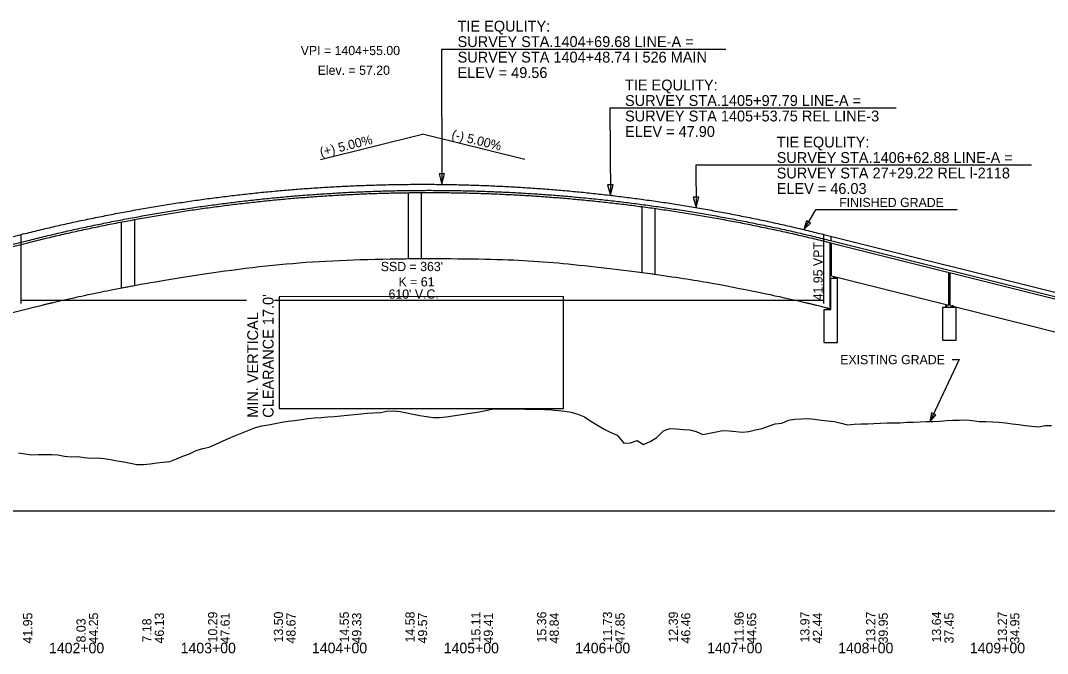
# Model space of a CAD drawing. Extents: x 2360994 to 2383826, y 330623 to 403123.
# Drawn here: x 2372575 to 2373355, y 371764 to 372245 of the extents above; entities that cross this region are included whole.
import ezdxf

# ---------------------------------------------------------------- set-up
doc = ezdxf.new("R2010")
doc.units = 0
for name, color, linetype in [('RD_DDB_GradeTX', 7, 'Continuous'), ('RD_DDB_Profile_EX', 7, 'Continuous'), ('RD_DDB_Profile_Lbl', 7, 'Continuous'), ('RD_DDB_Profile_PR', 7, 'Continuous'), ('RD_DDB_StaTX', 7, 'Continuous'), ('RD_DDB_StripGrade', 7, 'Continuous'), ('RD_DDB_VCLbl', 7, 'Continuous'), ('RD_GPK_Profile_Cell', 7, 'Continuous'), ('RD_TX_Profile', 7, 'Continuous'), ('RD_XS_Bridge', 7, 'Continuous')]:
    doc.layers.add(name, color=color, linetype=linetype)

msp = doc.modelspace()

# ---------------------------------------------------------------- linework, layer by layer
at = {"layer": 'RD_DDB_GradeTX'}
for p in [(2372802.95, 372139.48), (2372958.18, 372139.48)]:
    msp.add_line(p, (2372880.57, 372158.88), dxfattribs=at)
at = {"layer": 'RD_DDB_Profile_EX'}
for points in [[(2372573.57, 371916.75), (2372578.57, 371916.05), (2372583.57, 371915.41), (2372588.57, 371915.52), (2372593.57, 371915.64), (2372598.57, 371915.52), (2372603.57, 371915.17), (2372608.57, 371914.39), (2372613.57, 371913.78), (2372618.57, 371913.91), (2372623.57, 371913.26), (2372628.57, 371912.73), (2372633.57, 371912.9), (2372638.57, 371912.49), (2372643.57, 371911.7), (2372648.57, 371910.8), (2372653.57, 371909.99), (2372658.57, 371909.04), (2372663.57, 371908.05), (2372668.57, 371908.04), (2372673.57, 371908.57), (2372678.57, 371909.11), (2372683.57, 371909.65), (2372688.57, 371910.2), (2372693.57, 371912.18), (2372698.57, 371914.36), (2372703.57, 371916.04), (2372708.57, 371918.68), (2372713.57, 371920.08), (2372718.57, 371921.1), (2372723.57, 371923.41), (2372728.57, 371925.77), (2372733.57, 371927.84), (2372738.57, 371929.86), (2372743.57, 371931.9), (2372748.57, 371933.95), (2372753.57, 371936.04), (2372758.57, 371937.2), (2372763.57, 371938.15), (2372768.57, 371939.11), (2372773.57, 371940.08), (2372778.57, 371940.79), (2372783.57, 371941.48), (2372788.57, 371942.14), (2372793.57, 371942.79), (2372798.57, 371943.3), (2372803.57, 371943.68), (2372808.57, 371944.07), (2372813.57, 371944.46), (2372818.57, 371944.93), (2372823.57, 371945.42), (2372828.57, 371945.93), (2372833.57, 371946.38), (2372838.57, 371946.83), (2372843.57, 371947.22), (2372848.57, 371947.37), (2372853.57, 371948.38), (2372858.57, 371948.76), (2372863.57, 371948.1), (2372868.57, 371947.1), (2372873.57, 371946.18)], [(2372873.57, 371946.18), (2372878.57, 371945.19), (2372883.57, 371944.46), (2372888.57, 371943.56), (2372893.57, 371943.59), (2372898.57, 371944.18), (2372903.57, 371944.88), (2372908.57, 371945.56), (2372913.57, 371946.34), (2372918.57, 371947.12), (2372923.57, 371947.99), (2372928.57, 371949.04), (2372933.57, 371949.85), (2372938.57, 371950.13), (2372943.57, 371950.35), (2372948.57, 371950.26), (2372953.57, 371950.16), (2372958.57, 371950.05), (2372963.57, 371949.96), (2372968.57, 371949.87), (2372973.57, 371949.76), (2372978.57, 371949.52), (2372983.57, 371949.03), (2372988.57, 371948.53), (2372993.57, 371947.59), (2372998.57, 371946.29), (2373003.57, 371944.13), (2373008.57, 371940.76), (2373013.57, 371937.7), (2373018.57, 371934.68), (2373023.57, 371932.37), (2373028.57, 371930.22), (2373033.57, 371924.25), (2373038.57, 371924.34), (2373043.57, 371926.11), (2373048.57, 371923.15), (2373053.57, 371925.37), (2373058.57, 371928.46), (2373063.57, 371933.52), (2373068.57, 371935.29), (2373073.57, 371934.95), (2373078.57, 371934.6), (2373083.57, 371934.15), (2373088.57, 371933.09), (2373093.57, 371930.85), (2373098.57, 371931.74), (2373103.57, 371932.77), (2373108.57, 371933.8), (2373113.57, 371933.45), (2373118.57, 371932.91), (2373123.57, 371932.38), (2373128.57, 371933.07), (2373133.57, 371934.18), (2373138.57, 371935.31), (2373143.57, 371937.03), (2373148.57, 371938.81), (2373153.57, 371939.31), (2373158.57, 371941.61), (2373163.57, 371942.28), (2373168.57, 371942.63), (2373173.57, 371942.97), (2373178.57, 371942.42), (2373183.57, 371941.73), (2373188.57, 371941.1), (2373193.57, 371940.52), (2373198.57, 371939.3), (2373203.57, 371938.07), (2373208.57, 371938.66), (2373213.57, 371938.73), (2373218.57, 371938.79), (2373223.57, 371939.1), (2373228.57, 371939.4), (2373233.57, 371939.62), (2373238.57, 371939.55), (2373243.57, 371939.57), (2373248.57, 371939.99), (2373253.57, 371940.16), (2373258.57, 371940.32), (2373263.57, 371940.49), (2373268.57, 371940.65), (2373273.57, 371940.81), (2373278.57, 371941.43), (2373283.57, 371941.5), (2373288.57, 371941.66), (2373293.57, 371941.82), (2373298.57, 371941.44), (2373303.57, 371940.53), (2373308.57, 371940.63), (2373313.57, 371940.45), (2373318.57, 371940.09), (2373323.57, 371939.49), (2373328.57, 371938.88), (2373333.57, 371938.27), (2373338.57, 371937.66), (2373343.57, 371937.05), (2373348.57, 371936.44), (2373353.57, 371937.64), (2373358.57, 371937.56)]]:
    msp.add_lwpolyline(points, dxfattribs=at)
at = {"layer": 'RD_DDB_Profile_PR'}
for p, q in [((2372206.57, 371990.38), (2372575.57, 372082.63)), ((2373185.57, 372082.63), (2373396.07, 372030.01))]:
    msp.add_line(p, q, dxfattribs=at)
msp.add_spline([(2372575.57, 372082.63), (2372587.77, 372085.62), (2372599.97, 372088.49), (2372612.17, 372091.23), (2372624.37, 372093.86), (2372636.57, 372096.36), (2372648.77, 372098.74), (2372660.97, 372100.99), (2372673.17, 372103.13), (2372685.37, 372105.14), (2372697.57, 372107.03), (2372709.77, 372108.8), (2372721.97, 372110.45), (2372734.17, 372111.97), (2372746.37, 372113.38), (2372758.57, 372114.66), (2372770.77, 372115.82), (2372782.97, 372116.85), (2372795.17, 372117.77), (2372807.37, 372118.56), (2372819.57, 372119.23), (2372831.77, 372119.78), (2372843.97, 372120.21), (2372856.17, 372120.51), (2372868.37, 372120.7), (2372880.57, 372120.76), (2372892.77, 372120.7), (2372904.97, 372120.51), (2372917.17, 372120.21), (2372929.37, 372119.78), (2372941.57, 372119.23), (2372953.77, 372118.56), (2372965.97, 372117.77), (2372978.17, 372116.85), (2372990.37, 372115.82), (2373002.57, 372114.66), (2373014.77, 372113.38), (2373026.97, 372111.97), (2373039.17, 372110.45), (2373051.37, 372108.8), (2373063.57, 372107.03), (2373075.77, 372105.14), (2373087.97, 372103.13), (2373100.17, 372100.99), (2373112.37, 372098.74), (2373124.57, 372096.36), (2373136.77, 372093.86), (2373148.97, 372091.23), (2373161.17, 372088.49), (2373173.37, 372085.62), (2373185.57, 372082.63)], degree=3, dxfattribs=at)
at = {"layer": 'RD_DDB_VCLbl'}
for p, q in [((2372575.57, 372030.13), (2372575.57, 372082.63)), ((2373185.57, 372030.13), (2373185.57, 372082.63)), ((2372575.57, 372032.63), (2372746.9, 372032.63)), ((2372768, 372032.63), (2373185.57, 372032.63))]:
    msp.add_line(p, q, dxfattribs=at)
at = {"layer": 'RD_GPK_Profile_Cell'}
msp.add_line((2368825.57, 371872.88), (2373925.57, 371872.88), dxfattribs=at)
at = {"layer": 'RD_TX_Profile'}
for p, q in [((2373111.11, 372223.22), (2372902.19, 372223.22)), ((2373240.51, 372178.49), (2373029.43, 372178.49)), ((2373343.32, 372135.18), (2373144.67, 372135.18)), ((2373286.69, 372101.46), (2373192.13, 372101.46))]:
    msp.add_line(p, q, dxfattribs=at)
for points in [[(2372902.19, 372223.22), (2372895.1, 372223.22), (2372895.24, 372120.67)], [(2373029.43, 372178.49), (2373022.87, 372178.49), (2373023.35, 372112.4)], [(2373144.67, 372135.18), (2373088.27, 372135.18), (2373088.44, 372103.05)], [(2373192.13, 372101.46), (2373179.27, 372101.46), (2373170.35, 372086.35)], [(2373283.02, 371987.58), (2373288.36, 371987.58), (2373266.11, 371940.27)]]:
    msp.add_lwpolyline(points, dxfattribs=at)
for points in [[(2372893.1, 372128.62), (2372895.24, 372120.67), (2372897.36, 372128.63)], [(2373021.16, 372120.34), (2373023.35, 372112.4), (2373025.42, 372120.37)], [(2373086.27, 372110.99), (2373088.44, 372103.05), (2373090.53, 372111.01)], [(2373172.23, 372093.09), (2373170.35, 372086.35), (2373175.35, 372091.25)], [(2372771.69, 372035.41), (2372771.69, 371950.41), (2372987.68, 371950.41), (2372987.68, 372035.45)], [(2373267.35, 371947.15), (2373266.11, 371940.27), (2373270.63, 371945.61)]]:
    msp.add_lwpolyline(points, close=True, dxfattribs=at)
at = {"layer": 'RD_XS_Bridge'}
for p, q in [((2372869.83, 372064.4), (2372869.83, 372114.4)), ((2372879.83, 372064.49), (2372879.83, 372114.49)), ((2373047.41, 372053.75), (2373047.41, 372103.77)), ((2373057.41, 372052.38), (2373057.41, 372102.4)), ((2372651.91, 372042.09), (2372651.91, 372092.13)), ((2372661.91, 372043.97), (2372661.91, 372094.01)), ((2372227.91, 371989.88), (2372580.57, 372078.05)), ((2372227.91, 371988.22), (2372580.57, 372076.38)), ((2373190.33, 372026.37), (2373190.33, 372076.19)), ((2373190.57, 372078.05), (2373396.07, 372026.67)), ((2373190.57, 372076.38), (2373396.07, 372025.01)), ((2373190.83, 372081.23), (2373190.83, 372077.9)), ((2373191.33, 372051.15), (2373191.33, 372076.19)), ((2373191.33, 372051.15), (2373280.49, 372028.86)), ((2373280.49, 372028.86), (2373280.49, 372053.9)), ((2373281.49, 372028.61), (2373281.49, 372053.65)), ((2373190.83, 372049.47), (2373195.83, 372049.47)), ((2373190.83, 372025.62), (2373190.83, 372049.47)), ((2373195.83, 372000.62), (2373195.83, 372049.47)), ((2373275.99, 372002.49), (2373275.99, 372027.49)), ((2373275.99, 372027.49), (2373280.99, 372027.49)), ((2373280.99, 372027.49), (2373285.99, 372027.49)), ((2373281.49, 372028.61), (2373396.07, 371999.97)), ((2373285.99, 372002.49), (2373285.99, 372027.49)), ((2372483.16, 372001.96), (2372581.12, 372026.45)), ((2373185.83, 372000.62), (2373185.83, 372025.62)), ((2373185.83, 372025.62), (2373190.83, 372025.62)), ((2373185.83, 372000.62), (2373195.83, 372000.62)), ((2373275.99, 372002.49), (2373285.99, 372002.49))]:
    msp.add_line(p, q, dxfattribs=at)
for points in [[(2373193.08, 372049.47), (2373193.08, 372050.72), (2373193.58, 372050.72), (2373193.58, 372049.47)], [(2373188.08, 372025.62), (2373188.08, 372026.87), (2373188.58, 372026.87), (2373188.58, 372025.62)], [(2373278.24, 372027.49), (2373278.24, 372028.74), (2373278.74, 372028.74), (2373278.74, 372027.49)], [(2373283.24, 372027.49), (2373283.24, 372028.74), (2373283.74, 372028.74), (2373283.74, 372027.49)]]:
    msp.add_lwpolyline(points, close=True, dxfattribs=at)
for points in [[(2372580.57, 372078.05), (2372592.77, 372081.04), (2372604.97, 372083.9), (2372617.17, 372086.65), (2372629.37, 372089.27), (2372641.57, 372091.77), (2372653.77, 372094.15), (2372665.97, 372096.41), (2372678.17, 372098.54), (2372690.37, 372100.56), (2372702.57, 372102.45), (2372714.77, 372104.22), (2372726.97, 372105.86), (2372739.17, 372107.39), (2372751.37, 372108.79), (2372763.57, 372110.07), (2372775.77, 372111.23), (2372787.97, 372112.27), (2372800.17, 372113.18), (2372812.37, 372113.98), (2372824.57, 372114.65), (2372836.77, 372115.2), (2372848.97, 372115.62), (2372861.17, 372115.93), (2372873.37, 372116.11), (2372885.57, 372116.17), (2372897.77, 372116.11), (2372909.97, 372115.93), (2372922.17, 372115.62), (2372934.37, 372115.2), (2372946.57, 372114.65), (2372958.77, 372113.98), (2372970.97, 372113.18), (2372983.17, 372112.27), (2372995.37, 372111.23), (2373007.57, 372110.07), (2373019.77, 372108.79), (2373031.97, 372107.39), (2373044.17, 372105.86), (2373056.37, 372104.22), (2373068.57, 372102.45), (2373080.77, 372100.56), (2373092.97, 372098.54), (2373105.17, 372096.41), (2373117.37, 372094.15), (2373129.57, 372091.77), (2373141.77, 372089.27), (2373153.97, 372086.65), (2373166.17, 372083.9), (2373178.37, 372081.04), (2373190.57, 372078.05)], [(2372580.57, 372076.38), (2372592.77, 372079.37), (2372604.97, 372082.24), (2372617.17, 372084.98), (2372629.37, 372087.61), (2372641.57, 372090.11), (2372653.77, 372092.49), (2372665.97, 372094.74), (2372678.17, 372096.88), (2372690.37, 372098.89), (2372702.57, 372100.78), (2372714.77, 372102.55), (2372726.97, 372104.2), (2372739.17, 372105.72), (2372751.37, 372107.13), (2372763.57, 372108.41), (2372775.77, 372109.57), (2372787.97, 372110.6), (2372800.17, 372111.52), (2372812.37, 372112.31), (2372824.57, 372112.98), (2372836.77, 372113.53), (2372848.97, 372113.96), (2372861.17, 372114.26), (2372873.37, 372114.45), (2372885.57, 372114.51), (2372897.77, 372114.45), (2372909.97, 372114.26), (2372922.17, 372113.96), (2372934.37, 372113.53), (2372946.57, 372112.98), (2372958.77, 372112.31), (2372970.97, 372111.52), (2372983.17, 372110.6), (2372995.37, 372109.57), (2373007.57, 372108.41), (2373019.77, 372107.13), (2373031.97, 372105.72), (2373044.17, 372104.2), (2373056.37, 372102.55), (2373068.57, 372100.78), (2373080.77, 372098.89), (2373092.97, 372096.88), (2373105.17, 372094.74), (2373117.37, 372092.49), (2373129.57, 372090.11), (2373141.77, 372087.61), (2373153.97, 372084.98), (2373166.17, 372082.24), (2373178.37, 372079.37), (2373190.57, 372076.38)], [(2372869.83, 372064.37), (2372875.57, 372064.47), (2372879.83, 372064.52)], [(2373047.41, 372053.71), (2373055.55, 372052.67), (2373057.41, 372052.43)], [(2372651.91, 372042.16), (2372653.57, 372042.45), (2372657.57, 372043.15), (2372661.57, 372043.85), (2372661.91, 372043.9)]]:
    msp.add_spline(points, degree=3, dxfattribs=at)
msp.add_open_spline([(2372581.1, 372026.45), (2372584.28, 372027.23), (2372587.46, 372028.01), (2372592.21, 372029.17), (2372593.79, 372029.56), (2372596.96, 372030.31), (2372598.54, 372030.69), (2372603.3, 372031.8), (2372606.47, 372032.53), (2372612.81, 372033.96), (2372628.65, 372037.49), (2372669.87, 372045.86), (2372758.66, 372059.74), (2372834.8, 372064.5), (2372936.33, 372064.5), (2372987.09, 372061.33), (2373063.21, 372051.81), (2373101.27, 372045.87), (2373142.48, 372037.49), (2373158.33, 372033.96), (2373164.66, 372032.53), (2373167.84, 372031.8), (2373172.59, 372030.69), (2373174.17, 372030.31), (2373177.34, 372029.56), (2373178.92, 372029.17), (2373183.41, 372028.08), (2373186.33, 372027.36), (2373190.33, 372026.37)], degree=3, dxfattribs=at)

# ---------------------------------------------------------------- texts
at = {"layer": 'RD_DDB_GradeTX'}
for s, rotation, p in [('(-) 5.00%', 345.96376, (2372902.15, 372155.55)), ('(+) 5.00%', 14.03624, (2372803.5, 372141.68))]:
    msp.add_text(s, height=7, rotation=rotation, dxfattribs=at).set_placement(p)
at = {"layer": 'RD_DDB_Profile_Lbl'}
for s, p in [('VPI = 1404+55.00', (2372788.01, 372218.88)), ('Elev. = 57.20', (2372800.9, 372203.88))]:
    msp.add_text(s, height=7, dxfattribs=at).set_placement(p)
at = {"layer": 'RD_DDB_StaTX'}
for s, p in [('1402+00', (2372596.77, 371764.56)), ('1403+00', (2372696.8, 371764.56)), ('1404+00', (2372796.55, 371764.56)), ('1405+00', (2372896.69, 371764.56)), ('1406+00', (2372996.46, 371764.56)), ('1407+00', (2373096.81, 371764.56)), ('1408+00', (2373196.35, 371764.56)), ('1409+00', (2373296.45, 371764.56))]:
    msp.add_text(s, height=8, dxfattribs=at).set_placement(p)
at = {"layer": 'RD_DDB_StripGrade'}
for s, p in [('41.95 VPT', (2373184.57, 372032.63)), ('41.95', (2372584.08, 371772.02)), ('44.25', (2372634.08, 371772.02)), ('46.13', (2372684.08, 371772.02)), ('10.29', (2372724.59, 371772.81)), ('47.61', (2372734.08, 371772.02)), ('13.50', (2372774.59, 371772.81)), ('48.67', (2372784.08, 371772.02)), ('14.55', (2372824.59, 371772.81)), ('49.33', (2372834.08, 371772.02)), ('14.58', (2372874.59, 371772.81)), ('49.57', (2372884.08, 371772.02)), ('15.11', (2372924.59, 371772.81)), ('49.41', (2372934.08, 371772.02)), ('15.36', (2372974.59, 371772.81)), ('48.84', (2372984.08, 371772.02)), ('11.73', (2373024.59, 371772.81)), ('47.85', (2373034.08, 371772.02)), ('12.39', (2373074.59, 371772.81)), ('46.46', (2373084.08, 371772.02)), ('11.96', (2373124.59, 371772.81)), ('44.65', (2373134.08, 371772.02)), ('13.97', (2373174.59, 371772.81)), ('42.44', (2373184.08, 371772.02)), ('13.27', (2373224.59, 371772.81)), ('39.95', (2373234.08, 371772.02)), ('13.64', (2373274.59, 371772.81)), ('37.45', (2373284.08, 371772.02)), ('13.27', (2373324.59, 371772.81)), ('34.95', (2373334.08, 371772.02)), ('8.03', (2372624.59, 371772.81)), ('7.18', (2372674.59, 371772.81))]:
    msp.add_text(s, height=7, rotation=90, dxfattribs=at).set_placement(p)
at = {"layer": 'RD_DDB_VCLbl'}
for s, p in [("SSD = 363'", (2372848.87, 372054.81)), ('K = 61', (2372862.34, 372043.2)), ("610' V.C.", (2372854.74, 372033.88))]:
    msp.add_text(s, height=7, dxfattribs=at).set_placement(p)
at = {"layer": 'RD_TX_Profile'}
for s, height, p in [('TIE EQULITY:', 8.2353, (2372907.19, 372236.75)), ('SURVEY STA.1404+69.68 LINE-A =', 8.2353, (2372907.19, 372224.99)), ('SURVEY STA 1404+48.74 I 526 MAIN', 8.2353, (2372907.19, 372213.22)), ('ELEV = 49.56', 8.2353, (2372907.19, 372201.46)), ('TIE EQULITY:', 8.2353, (2373034.43, 372192.02)), ('SURVEY STA.1405+97.79 LINE-A =', 8.2353, (2373034.43, 372180.26)), ('SURVEY STA 1405+53.75 REL LINE-3', 8.2353, (2373034.43, 372168.49)), ('ELEV = 47.90', 8.2353, (2373034.43, 372156.73)), ('TIE EQULITY:', 8.2353, (2373149.67, 372148.71)), ('SURVEY STA.1406+62.88 LINE-A =', 8.2353, (2373149.67, 372136.95)), ('SURVEY STA 27+29.22 REL l-2118', 8.2353, (2373149.67, 372125.18)), ('ELEV = 46.03', 8.2353, (2373149.67, 372113.42)), ('FINISHED GRADE', 7, (2373197.13, 372103.46)), ('EXISTING GRADE', 7, (2373197.9, 371984.08))]:
    msp.add_text(s, height=height, dxfattribs=at).set_placement(p)
for s, p in [("CLEARANCE 17.0'", (2372767.4, 371943.42)), ('MIN. VERTICAL', (2372755.63, 371943.42))]:
    msp.add_text(s, height=8.2353, rotation=90, dxfattribs=at).set_placement(p)

doc.saveas('drawing.dxf')
